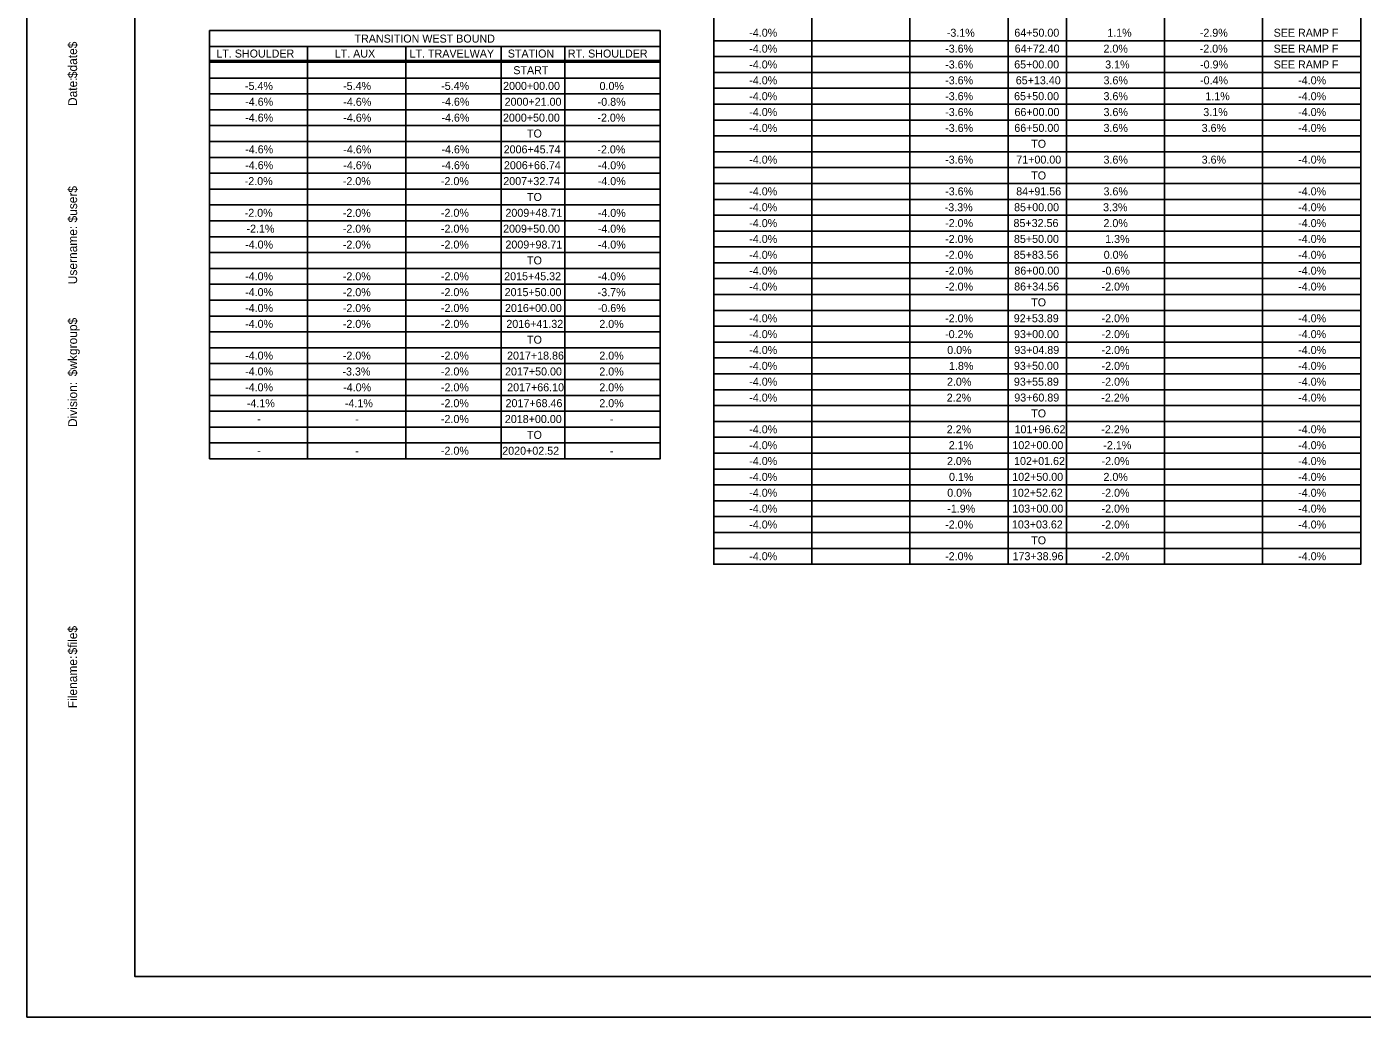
# Model space of a CAD drawing. Extents: x -15319374 to 1762012, y 465773 to 3693661.
# Drawn here: x -15317328 to -15316827, y 3691313 to 3691684 of the extents above; entities that cross this region are included whole.
import ezdxf

# ---------------------------------------------------------------- set-up
doc = ezdxf.new("R2010")
doc.units = 0
for name, color, linetype in [('BORDER', 7, 'Continuous'), ('DIMENSIONS', 7, 'Continuous'), ('PLOT BOUNDARY', 7, 'Continuous')]:
    doc.layers.add(name, color=color, linetype=linetype)

msp = doc.modelspace()

# ---------------------------------------------------------------- linework, layer by layer
at = {"layer": 'BORDER'}
for p, q in [((-15317070.51, 3691827.08), (-15317070.51, 3691482.47)), ((-15317033.74, 3691827.08), (-15317033.74, 3691482.47)), ((-15316996.97, 3691827.08), (-15316996.97, 3691482.47)), ((-15316960.21, 3691827.08), (-15316960.21, 3691482.47)), ((-15316938.33, 3691827.08), (-15316938.33, 3691482.47)), ((-15316901.56, 3691827.08), (-15316901.56, 3691482.47)), ((-15316864.8, 3691827.08), (-15316864.8, 3691482.47)), ((-15316828.03, 3691827.08), (-15316828.03, 3691482.47)), ((-15317070.51, 3691821.2), (-15317070.51, 3691482.47)), ((-15317070.51, 3691678.58), (-15316828.03, 3691678.58)), ((-15317259.46, 3691676.41), (-15317259.46, 3691558.21)), ((-15317222.69, 3691676.41), (-15317222.69, 3691521.96)), ((-15317185.92, 3691676.41), (-15317185.92, 3691521.96)), ((-15317150.15, 3691676.41), (-15317150.15, 3691521.96)), ((-15317126.28, 3691676.41), (-15317126.28, 3691521.96)), ((-15317259.46, 3691671.13), (-15317090.51, 3691671.13)), ((-15317259.46, 3691670.53), (-15317090.51, 3691670.53)), ((-15317070.51, 3691672.64), (-15316828.03, 3691672.64)), ((-15317259.46, 3691664.59), (-15317090.51, 3691664.59)), ((-15317259.46, 3691664.59), (-15317090.51, 3691664.59)), ((-15317259.46, 3691664.59), (-15317090.51, 3691664.59)), ((-15317070.51, 3691666.69), (-15316828.03, 3691666.69)), ((-15317259.46, 3691658.64), (-15317090.51, 3691658.64)), ((-15317070.51, 3691660.75), (-15316828.03, 3691660.75)), ((-15317070.51, 3691654.81), (-15316828.03, 3691654.81)), ((-15317259.46, 3691652.7), (-15317090.51, 3691652.7)), ((-15317070.51, 3691648.87), (-15316828.03, 3691648.87)), ((-15317259.46, 3691646.76), (-15317090.51, 3691646.76)), ((-15317259.46, 3691640.82), (-15317090.51, 3691640.82)), ((-15317070.51, 3691642.92), (-15316828.03, 3691642.92)), ((-15317259.46, 3691634.87), (-15317090.51, 3691634.87)), ((-15317070.51, 3691636.98), (-15316828.03, 3691636.98)), ((-15317259.46, 3691628.93), (-15317090.51, 3691628.93)), ((-15317070.51, 3691631.04), (-15316828.03, 3691631.04)), ((-15317070.51, 3691625.1), (-15316828.03, 3691625.1)), ((-15317259.46, 3691622.99), (-15317090.51, 3691622.99)), ((-15317070.51, 3691619.15), (-15316828.03, 3691619.15)), ((-15317259.46, 3691617.05), (-15317090.51, 3691617.05)), ((-15317070.51, 3691613.21), (-15316828.03, 3691613.21)), ((-15317259.46, 3691611.1), (-15317090.51, 3691611.1)), ((-15317259.46, 3691605.16), (-15317090.51, 3691605.16)), ((-15317070.51, 3691607.27), (-15316828.03, 3691607.27)), ((-15317259.46, 3691599.22), (-15317090.51, 3691599.22)), ((-15317070.51, 3691601.32), (-15316828.03, 3691601.32)), ((-15317259.46, 3691593.28), (-15317090.51, 3691593.28)), ((-15317070.51, 3691595.38), (-15316828.03, 3691595.38)), ((-15317070.51, 3691589.44), (-15316828.03, 3691589.44)), ((-15317259.46, 3691587.33), (-15317090.51, 3691587.33)), ((-15317070.51, 3691583.5), (-15316828.03, 3691583.5)), ((-15317259.46, 3691581.39), (-15317090.51, 3691581.39)), ((-15317259.46, 3691575.45), (-15317090.51, 3691575.45)), ((-15317070.51, 3691577.55), (-15316828.03, 3691577.55)), ((-15317259.46, 3691569.5), (-15317090.51, 3691569.5)), ((-15317070.51, 3691571.61), (-15316828.03, 3691571.61)), ((-15317259.46, 3691563.56), (-15317090.51, 3691563.56)), ((-15317070.51, 3691565.67), (-15316828.03, 3691565.67)), ((-15317070.51, 3691559.73), (-15316828.03, 3691559.73)), ((-15317259.46, 3691557.62), (-15317090.51, 3691557.62)), ((-15317070.51, 3691553.78), (-15316828.03, 3691553.78)), ((-15317259.46, 3691551.68), (-15317090.51, 3691551.68)), ((-15317259.46, 3691545.73), (-15317090.51, 3691545.73)), ((-15317070.51, 3691547.84), (-15316828.03, 3691547.84)), ((-15317259.46, 3691539.79), (-15317090.51, 3691539.79)), ((-15317070.51, 3691541.9), (-15316828.03, 3691541.9)), ((-15317259.46, 3691533.85), (-15317090.51, 3691533.85)), ((-15317070.51, 3691535.95), (-15316828.03, 3691535.95)), ((-15317070.51, 3691530.01), (-15316828.03, 3691530.01)), ((-15317259.46, 3691527.91), (-15317090.51, 3691527.91)), ((-15317070.51, 3691524.07), (-15316828.03, 3691524.07)), ((-15317259.46, 3691521.96), (-15317090.51, 3691521.96)), ((-15317070.51, 3691518.13), (-15316828.03, 3691518.13)), ((-15317070.51, 3691512.18), (-15316828.03, 3691512.18)), ((-15317070.51, 3691506.24), (-15316828.03, 3691506.24)), ((-15317070.51, 3691500.3), (-15316828.03, 3691500.3)), ((-15317070.51, 3691494.36), (-15316828.03, 3691494.36)), ((-15317070.51, 3691488.41), (-15316828.03, 3691488.41)), ((-15317070.51, 3691482.47), (-15316828.03, 3691482.47))]:
    msp.add_line(p, q, dxfattribs=at)
for points in [[(-15317287.5, 3691853.02), (-15316487.5, 3691853.02), (-15316487.5, 3691328.02), (-15317287.5, 3691328.02)], [(-15317070.51, 3691827.08), (-15316828.03, 3691827.08), (-15316828.03, 3691482.47), (-15317070.51, 3691482.47)], [(-15317259.46, 3691676.41), (-15317090.51, 3691676.41), (-15317090.51, 3691521.96), (-15317259.46, 3691521.96)]]:
    msp.add_lwpolyline(points, close=True, dxfattribs=at)
msp.add_lwpolyline([(-15317259.46, 3691676.41), (-15317259.46, 3691682.35), (-15317090.51, 3691682.35), (-15317090.51, 3691676.41)], dxfattribs=at)
at = {"layer": 'PLOT BOUNDARY'}
msp.add_lwpolyline([(-15317327.97, 3691312.73), (-15316477.97, 3691312.73), (-15316477.97, 3691862.73), (-15317327.97, 3691862.73)], close=True, dxfattribs=at)

# ---------------------------------------------------------------- texts
at = {"layer": 'BORDER'}
for s, p in [('$date$', (-15317309.08, 3691664.55)), ('Date:', (-15317309.08, 3691654.11)), ('$user$', (-15317309.08, 3691610.48)), ('Username:', (-15317309.08, 3691587.36)), ('$wkgroup$', (-15317309.08, 3691552.87)), ('Division:', (-15317309.08, 3691533.85)), ('$file$', (-15317309.08, 3691448.65)), ('Filename:', (-15317309.08, 3691428.52))]:
    msp.add_text(s, height=3.348, rotation=90, dxfattribs=at).set_placement(p)
at = {"layer": 'DIMENSIONS'}
for s, p in [('-4.0%', (-15317057.18, 3691680.07)), ('-3.1%', (-15316983.15, 3691680.07)), ('64+50.00', (-15316957.84, 3691680.08)), ('-2.9%', (-15316888.33, 3691680.07)), ('SEE RAMP F', (-15316860.66, 3691680.07)), ('TRANSITION WEST BOUND', (-15317205.11, 3691677.88)), ('1.1%', (-15316923.02, 3691680.07)), ('LT. SHOULDER', (-15317256.9, 3691672.27)), ('LT. AUX', (-15317212.54, 3691672.27)), ('LT. TRAVELWAY', (-15317184.47, 3691672.27)), ('STATION', (-15317147.69, 3691672.27)), ('RT. SHOULDER', (-15317125.15, 3691672.27)), ('-4.0%', (-15317057.18, 3691674.12)), ('-3.6%', (-15316983.76, 3691674.12)), ('64+72.40', (-15316957.72, 3691674.14)), ('2.0%', (-15316924.43, 3691674.12)), ('-2.0%', (-15316888.37, 3691674.12)), ('SEE RAMP F', (-15316860.66, 3691674.12)), ('START', (-15317145.61, 3691666.04)), ('-4.0%', (-15317057.18, 3691668.18)), ('-3.6%', (-15316983.76, 3691668.18)), ('65+00.00', (-15316957.89, 3691668.2)), ('3.1%', (-15316923.79, 3691668.18)), ('-0.9%', (-15316888.23, 3691668.18)), ('SEE RAMP F', (-15316860.66, 3691668.18)), ('-5.4%', (-15317246.17, 3691660.15)), ('-5.4%', (-15317209.4, 3691660.13)), ('-5.4%', (-15317172.64, 3691660.15)), ('2000+00.00', (-15317149.43, 3691660.15)), ('0.0%', (-15317113.29, 3691660.13)), ('-4.0%', (-15317057.18, 3691662.24)), ('-3.6%', (-15316983.76, 3691662.24)), ('65+13.40', (-15316957.3, 3691662.25)), ('3.6%', (-15316924.41, 3691662.24)), ('-0.4%', (-15316888.23, 3691662.24)), ('-4.0%', (-15316851.46, 3691662.24)), ('-4.0%', (-15317057.18, 3691656.3)), ('-3.6%', (-15316983.76, 3691656.3)), ('65+50.00', (-15316957.93, 3691656.31)), ('3.6%', (-15316924.41, 3691656.3)), ('1.1%', (-15316886.25, 3691656.3)), ('-4.0%', (-15316851.46, 3691656.3)), ('-4.6%', (-15317246.08, 3691654.21)), ('-4.6%', (-15317209.31, 3691654.19)), ('-4.6%', (-15317172.54, 3691654.21)), ('2000+21.00', (-15317148.86, 3691654.21)), ('-0.8%', (-15317113.99, 3691654.19)), ('-4.0%', (-15317057.18, 3691650.35)), ('-3.6%', (-15316983.76, 3691650.35)), ('66+00.00', (-15316957.79, 3691650.37)), ('3.6%', (-15316924.41, 3691650.35)), ('3.1%', (-15316887.03, 3691650.35)), ('-4.0%', (-15316851.46, 3691650.35)), ('-4.6%', (-15317246.08, 3691648.26)), ('-4.6%', (-15317209.31, 3691648.25)), ('-4.6%', (-15317172.54, 3691648.26)), ('2000+50.00', (-15317149.48, 3691648.26)), ('-2.0%', (-15317114.09, 3691648.25)), ('TO', (-15317140.46, 3691642.32)), ('-4.0%', (-15317057.18, 3691644.41)), ('-3.6%', (-15316983.76, 3691644.41)), ('66+50.00', (-15316957.84, 3691644.43)), ('3.6%', (-15316924.41, 3691644.41)), ('3.6%', (-15316887.64, 3691644.41)), ('-4.0%', (-15316851.46, 3691644.41)), ('-4.6%', (-15317246.08, 3691636.38)), ('-4.6%', (-15317209.31, 3691636.36)), ('-4.6%', (-15317172.54, 3691636.38)), ('2006+45.74', (-15317149.22, 3691636.38)), ('-2.0%', (-15317114.09, 3691636.36)), ('TO', (-15316951.51, 3691638.48)), ('-4.6%', (-15317246.08, 3691630.44)), ('-4.6%', (-15317209.31, 3691630.42)), ('-4.6%', (-15317172.54, 3691630.44)), ('2006+66.74', (-15317149.12, 3691630.44)), ('-4.0%', (-15317113.95, 3691630.42)), ('-4.0%', (-15317057.18, 3691632.53)), ('-3.6%', (-15316983.76, 3691632.53)), ('71+00.00', (-15316957.11, 3691632.54)), ('3.6%', (-15316924.41, 3691632.53)), ('3.6%', (-15316887.64, 3691632.53)), ('-4.0%', (-15316851.46, 3691632.53)), ('TO', (-15316951.51, 3691626.6)), ('-2.0%', (-15317246.27, 3691624.49)), ('-2.0%', (-15317209.5, 3691624.48)), ('-2.0%', (-15317172.73, 3691624.49)), ('2007+32.74', (-15317149.36, 3691624.49)), ('-4.0%', (-15317113.95, 3691624.48)), ('-4.0%', (-15317057.18, 3691620.64)), ('-3.6%', (-15316983.76, 3691620.64)), ('84+91.56', (-15316957.13, 3691620.66)), ('3.6%', (-15316924.41, 3691620.64)), ('-4.0%', (-15316851.46, 3691620.64)), ('TO', (-15317140.46, 3691618.55)), ('-2.0%', (-15317246.27, 3691612.61)), ('-2.0%', (-15317209.5, 3691612.59)), ('-2.0%', (-15317172.73, 3691612.61)), ('2009+48.71', (-15317148.56, 3691612.61)), ('-4.0%', (-15317113.95, 3691612.59)), ('-4.0%', (-15317057.18, 3691614.7)), ('-3.3%', (-15316983.93, 3691614.7)), ('85+00.00', (-15316957.93, 3691614.71)), ('3.3%', (-15316924.57, 3691614.7)), ('-4.0%', (-15316851.46, 3691614.7)), ('-2.1%', (-15317245.61, 3691606.66)), ('-2.0%', (-15317209.5, 3691606.65)), ('-2.0%', (-15317172.73, 3691606.66)), ('2009+50.00', (-15317149.43, 3691606.66)), ('-4.0%', (-15317113.95, 3691606.65)), ('-4.0%', (-15317057.18, 3691608.75)), ('-2.0%', (-15316983.78, 3691608.75)), ('85+32.56', (-15316958.15, 3691608.77)), ('2.0%', (-15316924.43, 3691608.75)), ('-4.0%', (-15316851.46, 3691608.75)), ('-4.0%', (-15317246.12, 3691600.72)), ('-2.0%', (-15317209.5, 3691600.71)), ('-2.0%', (-15317172.73, 3691600.72)), ('2009+98.71', (-15317148.56, 3691600.72)), ('-4.0%', (-15317113.95, 3691600.71)), ('-4.0%', (-15317057.18, 3691602.81)), ('-2.0%', (-15316983.78, 3691602.81)), ('85+50.00', (-15316957.98, 3691602.83)), ('1.3%', (-15316923.79, 3691602.81)), ('-4.0%', (-15316851.46, 3691602.81)), ('-4.0%', (-15317057.18, 3691596.87)), ('-2.0%', (-15316983.78, 3691596.87)), ('85+83.56', (-15316958.05, 3691596.89)), ('0.0%', (-15316924.34, 3691596.87)), ('-4.0%', (-15316851.46, 3691596.87)), ('TO', (-15317140.46, 3691594.78)), ('-4.0%', (-15317057.18, 3691590.93)), ('-2.0%', (-15316983.78, 3691590.93)), ('86+00.00', (-15316957.84, 3691590.94)), ('-0.6%', (-15316925, 3691590.93)), ('-4.0%', (-15316851.46, 3691590.93)), ('-4.0%', (-15317246.12, 3691588.84)), ('-2.0%', (-15317209.5, 3691588.82)), ('-2.0%', (-15317172.73, 3691588.84)), ('2015+45.32', (-15317149.02, 3691588.84)), ('-4.0%', (-15317113.95, 3691588.82)), ('-4.0%', (-15317057.18, 3691584.98)), ('-2.0%', (-15316983.78, 3691584.98)), ('86+34.56', (-15316957.91, 3691585)), ('-2.0%', (-15316925.14, 3691584.98)), ('-4.0%', (-15316851.46, 3691584.98)), ('-4.0%', (-15317246.12, 3691582.89)), ('-2.0%', (-15317209.5, 3691582.88)), ('-2.0%', (-15317172.73, 3691582.89)), ('2015+50.00', (-15317148.86, 3691582.89)), ('-3.7%', (-15317113.99, 3691582.88)), ('-4.0%', (-15317246.12, 3691576.95)), ('-2.0%', (-15317209.5, 3691576.93)), ('-2.0%', (-15317172.73, 3691576.95)), ('2016+00.00', (-15317148.72, 3691576.95)), ('-0.6%', (-15317113.95, 3691576.93)), ('TO', (-15316951.51, 3691579.06)), ('-4.0%', (-15317246.12, 3691571.01)), ('-2.0%', (-15317209.5, 3691570.99)), ('-2.0%', (-15317172.73, 3691571.01)), ('2016+41.32', (-15317148.21, 3691571.01)), ('2.0%', (-15317113.38, 3691570.99)), ('-4.0%', (-15317057.18, 3691573.1)), ('-2.0%', (-15316983.78, 3691573.1)), ('92+53.89', (-15316958.05, 3691573.11)), ('-2.0%', (-15316925.14, 3691573.1)), ('-4.0%', (-15316851.46, 3691573.1)), ('TO', (-15317140.46, 3691565.07)), ('-4.0%', (-15317057.18, 3691567.16)), ('-0.2%', (-15316983.78, 3691567.16)), ('93+00.00', (-15316957.96, 3691567.17)), ('-2.0%', (-15316925.14, 3691567.16)), ('-4.0%', (-15316851.46, 3691567.16)), ('-4.0%', (-15317057.18, 3691561.21)), ('0.0%', (-15316982.98, 3691561.21)), ('93+04.89', (-15316957.86, 3691561.23)), ('-2.0%', (-15316925.14, 3691561.21)), ('-4.0%', (-15316851.46, 3691561.21)), ('-4.0%', (-15317246.12, 3691559.12)), ('-2.0%', (-15317209.5, 3691559.11)), ('-2.0%', (-15317172.73, 3691559.12)), ('2017+18.86', (-15317147.94, 3691559.12)), ('2.0%', (-15317113.38, 3691559.11)), ('-4.0%', (-15317057.18, 3691555.27)), ('1.8%', (-15316982.32, 3691555.27)), ('93+50.00', (-15316958, 3691555.29)), ('-2.0%', (-15316925.14, 3691555.27)), ('-4.0%', (-15316851.46, 3691555.27)), ('-4.0%', (-15317246.12, 3691553.18)), ('-3.3%', (-15317209.64, 3691553.16)), ('-2.0%', (-15317172.73, 3691553.18)), ('2017+50.00', (-15317148.7, 3691553.18)), ('2.0%', (-15317113.38, 3691553.16)), ('-4.0%', (-15317246.12, 3691547.24)), ('-4.0%', (-15317209.36, 3691547.22)), ('-2.0%', (-15317172.73, 3691547.24)), ('2017+66.10', (-15317147.9, 3691547.24)), ('2.0%', (-15317113.38, 3691547.22)), ('-4.0%', (-15317057.18, 3691549.33)), ('2.0%', (-15316983.08, 3691549.33)), ('93+55.89', (-15316958, 3691549.34)), ('-2.0%', (-15316925.14, 3691549.33)), ('-4.0%', (-15316851.46, 3691549.33)), ('-4.1%', (-15317245.46, 3691541.29)), ('-4.1%', (-15317208.7, 3691541.28)), ('-2.0%', (-15317172.73, 3691541.29)), ('2017+68.46', (-15317148.51, 3691541.29)), ('2.0%', (-15317113.38, 3691541.28)), ('-4.0%', (-15317057.18, 3691543.38)), ('2.2%', (-15316983.17, 3691543.38)), ('93+60.89', (-15316957.86, 3691543.4)), ('-2.2%', (-15316925.24, 3691543.38)), ('-4.0%', (-15316851.46, 3691543.38)), ('-2.0%', (-15317172.73, 3691535.35)), ('2018+00.00', (-15317148.77, 3691535.35)), ('TO', (-15316951.51, 3691537.46)), ('-', (-15317241.58, 3691535.35)), ('-', (-15317204.81, 3691535.34)), ('-', (-15317109.4, 3691535.34)), ('-4.0%', (-15317057.18, 3691531.5)), ('2.2%', (-15316983.17, 3691531.5)), ('101+96.62', (-15316957.76, 3691531.52)), ('-2.2%', (-15316925.24, 3691531.5)), ('-4.0%', (-15316851.46, 3691531.5)), ('TO', (-15317140.46, 3691529.41)), ('-4.0%', (-15317057.18, 3691525.56)), ('2.1%', (-15316982.41, 3691525.56)), ('102+00.00', (-15316958.57, 3691525.57)), ('-2.1%', (-15316924.48, 3691525.56)), ('-4.0%', (-15316851.46, 3691525.56)), ('-', (-15317241.58, 3691523.47)), ('-', (-15317204.81, 3691523.45)), ('-2.0%', (-15317172.73, 3691523.47)), ('2020+02.52', (-15317149.75, 3691523.47)), ('-', (-15317109.4, 3691523.45)), ('-4.0%', (-15317057.18, 3691519.61)), ('2.0%', (-15316983.08, 3691519.61)), ('102+01.62', (-15316957.94, 3691519.63)), ('-2.0%', (-15316925.14, 3691519.61)), ('-4.0%', (-15316851.46, 3691519.61)), ('-4.0%', (-15317057.18, 3691513.67)), ('0.1%', (-15316982.32, 3691513.67)), ('102+50.00', (-15316958.62, 3691513.69)), ('2.0%', (-15316924.43, 3691513.67)), ('-4.0%', (-15316851.46, 3691513.67)), ('-4.0%', (-15317057.18, 3691507.73)), ('0.0%', (-15316982.98, 3691507.73)), ('102+52.62', (-15316958.75, 3691507.74)), ('-2.0%', (-15316925.14, 3691507.73)), ('-4.0%', (-15316851.46, 3691507.73)), ('-4.0%', (-15317057.18, 3691501.79)), ('-1.9%', (-15316982.98, 3691501.79)), ('103+00.00', (-15316958.59, 3691501.8)), ('-2.0%', (-15316925.14, 3691501.79)), ('-4.0%', (-15316851.46, 3691501.79)), ('-4.0%', (-15317057.18, 3691495.84)), ('-2.0%', (-15316983.78, 3691495.84)), ('103+03.62', (-15316958.75, 3691495.86)), ('-2.0%', (-15316925.14, 3691495.84)), ('-4.0%', (-15316851.46, 3691495.84)), ('TO', (-15316951.51, 3691489.92)), ('-4.0%', (-15317057.18, 3691483.96)), ('-2.0%', (-15316983.78, 3691483.96)), ('173+38.96', (-15316958.5, 3691483.97)), ('-2.0%', (-15316925.14, 3691483.96)), ('-4.0%', (-15316851.46, 3691483.96))]:
    msp.add_text(s, height=3, dxfattribs=at).set_placement(p)

doc.saveas('drawing.dxf')
